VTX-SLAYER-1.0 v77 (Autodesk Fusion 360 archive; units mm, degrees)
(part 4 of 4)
sketch "Skizze5" plane through (0, 0, 0) normal (-1, 0, 0) x axis (0, -1, 0)
  curve K1 (-1.5, 6.1577) -> (-18.5, 6.1577)
  line L1 (-18.5, 0) -> (-18.5, 6.1577)
  line L2 (-1.5, 0) -> (-18.5, 0)
  line L3 (-1.5, 6.1577) -> (-1.5, 0)
  curve K2 (-10.9281, 8.2013) -> (-9.0719, 8.2013)
  arc A1 centre (-10, 8.5) radius 0.975 clockwise from (-9.0719, 8.2013) to (-10.9281, 8.2013)
extrude "Extrusion4" cut sketch "Skizze5" profile of A1 against normal blind 4
sketch "Skizze7" plane through (0, 0, 0) normal (0, 0, -1) x axis (1, 0, 0)
  line L1 (20, -1.5) -> (20, -18.5)
  line L2 (1.5, 0) -> (18.5, 0)
  line L3 (18.5, -20) -> (1.5, -20)
  line L4 (9.5607, -19.5607) -> (19.5607, -19.5607)
  line L5 (9.5607, -15.5607) -> (9.5607, -19.5607)
  line L6 (19.5607, -15.5607) -> (9.5607, -15.5607)
  line L7 (19.5607, -19.5607) -> (19.5607, -15.5607)
  line L8 (0, -18.5) -> (0, -1.5)
  arc A1 centre (18.5, -18.5) radius 1.5 clockwise from (20, -18.5) to (18.5, -20)
  arc A2 centre (18.5, -1.5) radius 1.5 clockwise from (18.5, 0) to (20, -1.5)
  arc A3 centre (1.5, -1.5) radius 1.5 clockwise from (0, -1.5) to (1.5, 0)
  arc A4 centre (1.5, -18.5) radius 1.5 clockwise from (1.5, -20) to (0, -18.5)
  point P14 (19.5607, -19.5607)
  point P15 (9.5607, -19.5607)
  point P17 (19.5607, -15.5607)
  horizontal L4
  vertical L5
  horizontal L6
  vertical L7
  midpoint A1 P14
  dimension "d25" distance P14 P15 = 10
  dimension "d26" distance P14 P17 = 4
extrude "Extrusion5" new body sketch "Skizze7" profile of L4 L5 L6 L7 along normal blind 7

design "M2 x 0.4mm Thread 5mm LONG SOCKET HEAD CAP SCREW"
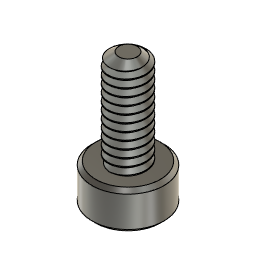
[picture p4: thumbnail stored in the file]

design "M3 x 0.5mm Thread 8mm LONG SOCKET HEAD CAP SCREW"
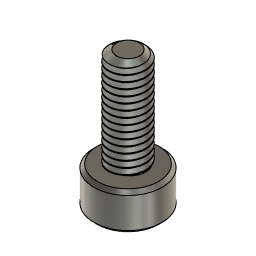
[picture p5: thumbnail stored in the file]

design "nut"
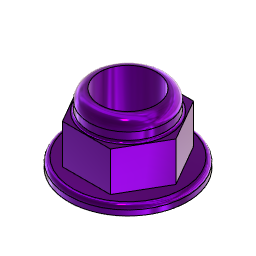
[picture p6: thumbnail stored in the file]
base_feature "Base Feature" bodies "nut (1)"
sketch "Sketch1" plane through (0, 0, 0) normal (1, 0, 0) x axis (0, 1, 0)
  line L1 (3.5, 35.5147) -> (15.2246, 35.5147)
  line L2 (3.5, 31.9) -> (3.5, 35.5147)
  line L3 (15.2246, 31.9) -> (3.5, 31.9)
  line L4 (15.2246, 35.5147) -> (15.2246, 31.9)
  line L5 (6.6576, 31.9) -> (12.1213, 31.9)
  line L6 (15.1073, 25.3) -> (3.6716, 25.3)
  line L7 (21.1207, 2.6841) -> (-6.8795, 2.6841)
  line L8 (21.1207, 25.3) -> (21.1207, 2.6841)
  line L9 (-6.8795, 25.3) -> (21.1207, 25.3)
  line L10 (-6.8795, 2.6841) -> (-6.8795, 25.3)
  point P4 (3.5, 31.9)
  point P9 (15.1073, 25.3)
  horizontal L1
  vertical L2
  horizontal L3
  vertical L4
  coincident P4 L5
  horizontal L7
  vertical L8
  horizontal L9
  vertical L10
  coincident P9 L9
extrude "Extrude3" cut sketch "Sketch1" along normal blind 90
extrude "Extrude4" cut of existing geometry blind -11
named bodies: "nut (1)"

design "M2 x 0.4mm Thread HEX NUT"
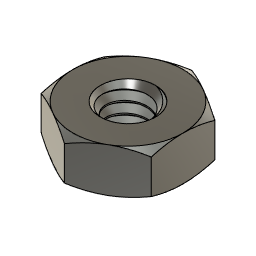
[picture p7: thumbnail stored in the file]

design "M3 x 0.5mm Thread 16mm LONG SOCKET HEAD CAP SCREW"
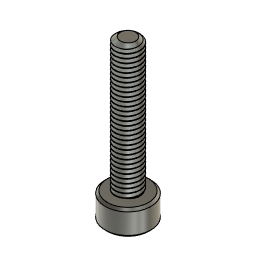
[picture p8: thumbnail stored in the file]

design "prop"
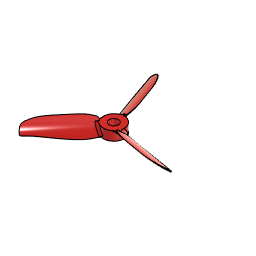
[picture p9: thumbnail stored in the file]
base_feature "Base Feature" bodies "prop (1)"
named bodies: "prop (1)"

design "M2 x 0.4mm Thread 20mm LONG SOCKET HEAD CAP SCREW"
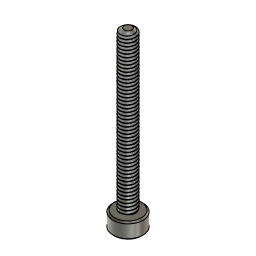
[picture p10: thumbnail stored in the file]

design "M2 x 0.4mm Thread 6mm LONG SOCKET HEAD CAP SCREW"
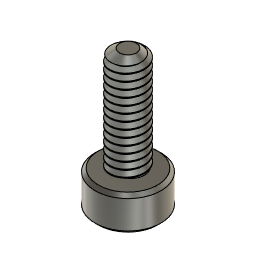
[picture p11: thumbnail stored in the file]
